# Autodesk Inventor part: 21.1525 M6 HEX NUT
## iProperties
Created: 2012-02
Part Number: 21.1525 M6 HEX NUT
Document SubType Name: Modeling
Designer: Administrator
Density: 7.85 g/cm^3
Material: Steel
Mass: 2.42169 g
Surface Area: 4.15922 cm^2
Volume: 0.308495 cm^3
Translation Standard: STEP AP203
FileName: 90591A151.step
PreProcessor: SolidWorks 2007
PostProcessor: Build: 236a, Release: 2009 RTM - Date: Fri 02/22/2008
Sent Units: MM
Uncertainty: 1e-05
Author: Administrator
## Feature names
1. Base1
